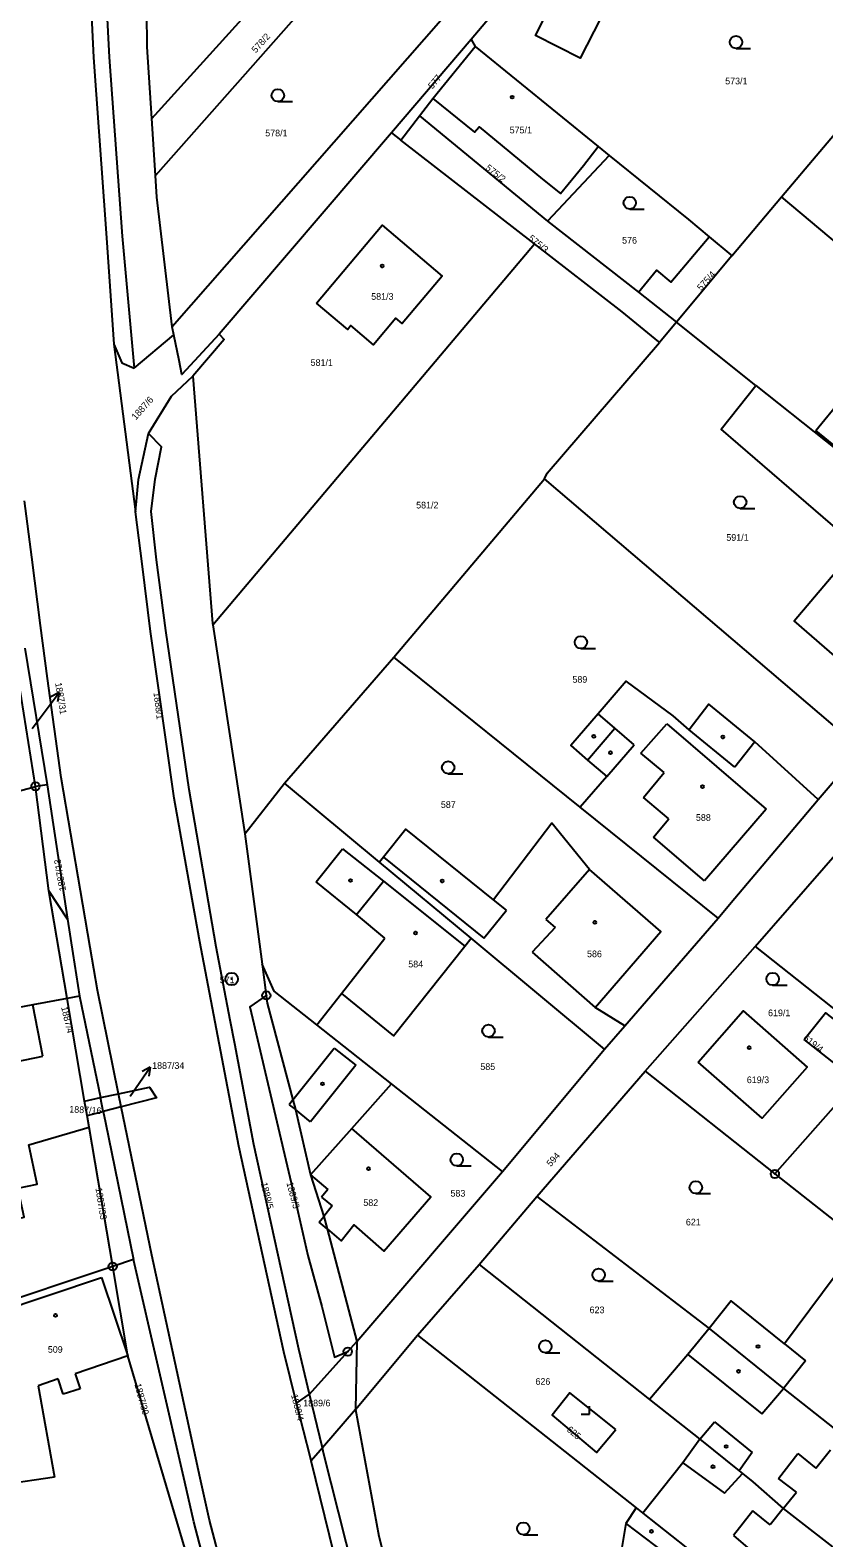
# Model space of a CAD drawing. Extents: x -587171 to -555306, y -1167727 to -1074732.
# Drawn here: x -561091.7 to -560995.9, y -1078068.2 to -1077886.5 of the extents above; entities that cross this region are included whole.
import ezdxf

# ---------------------------------------------------------------- set-up
doc = ezdxf.new("R2010")
doc.units = 0
for name, color, linetype in [('Hranice parcel', 7, 'Continuous'), ('Parcelní čísla', 7, 'Continuous'), ('Pop  PČ popisy', 7, 'Continuous'), ('Vnitřní kresba', 7, 'Continuous'), ('Značky bodu BP', 7, 'Continuous'), ('Značky budov', 7, 'Continuous'), ('Značky kultur', 7, 'Continuous')]:
    doc.layers.add(name, color=color, linetype=linetype)

msp = doc.modelspace()

# ---------------------------------------------------------------- linework, layer by layer
at = {"layer": 'Hranice parcel'}
for p, q in [((-561052.18, -1077876.5), (-561076.54, -1077904.04)), ((-561001.03, -1077906.61), (-560979.01, -1077880.52)), ((-561041.83, -1077885.03), (-561074.51, -1077922.26)), ((-561038.47, -1077887.64), (-561048.08, -1077898.88)), ((-561038.47, -1077887.64), (-561037.98, -1077888.46)), ((-561043.08, -1077894.73), (-561037.98, -1077888.46)), ((-561037.98, -1077888.46), (-561023.13, -1077900.55)), ((-561044.69, -1077896.83), (-561043.08, -1077894.73)), ((-561076.54, -1077904.04), (-561076.98, -1077897.15)), ((-561046.93, -1077899.77), (-561044.69, -1077896.83)), ((-561044.69, -1077896.83), (-561029.24, -1077909.55)), ((-561048.08, -1077898.88), (-561068.84, -1077923.15)), ((-561048.08, -1077898.88), (-561046.93, -1077899.77)), ((-561030.81, -1077912.27), (-561046.93, -1077899.77)), ((-561023.13, -1077900.55), (-561021.81, -1077901.62)), ((-561021.81, -1077901.62), (-561029.24, -1077909.55)), ((-561007.02, -1077913.69), (-561001.03, -1077906.61)), ((-560984.46, -1077920.52), (-561001.03, -1077906.61)), ((-561029.24, -1077909.55), (-561018.28, -1077918.07)), ((-561069.64, -1077958.17), (-561030.81, -1077912.27)), ((-561007.02, -1077913.69), (-561013.7, -1077921.7)), ((-561018.28, -1077918.07), (-561013.7, -1077921.7)), ((-561074.31, -1077923.24), (-561074.51, -1077922.26)), ((-561013.7, -1077921.7), (-561015.76, -1077924.17)), ((-561004.12, -1077929.33), (-561013.7, -1077921.7)), ((-561081.56, -1077924.36), (-561078.96, -1077944.55)), ((-561079.1, -1077927.23), (-561074.31, -1077923.24)), ((-561047.81, -1077962.07), (-561029.61, -1077940.57)), ((-560991.44, -1077973.16), (-561029.61, -1077940.57)), ((-561069.64, -1077958.17), (-561065.77, -1077983.36)), ((-561092.28, -1077961.01), (-561089.62, -1077977.48)), ((-561060.98, -1077977.27), (-561047.81, -1077962.07)), ((-561025.3, -1077980.17), (-561047.81, -1077962.07)), ((-561091.01, -1077977.66), (-561092.98, -1077965.31)), ((-561004.2, -1077996.95), (-560980.5, -1077969.74)), ((-560996.6, -1077979.25), (-560991.44, -1077973.16)), ((-561095.35, -1077978.85), (-561091.01, -1077977.66)), ((-561089.62, -1077977.48), (-561091.01, -1077977.66)), ((-561089.4, -1077990.23), (-561091.01, -1077977.66)), ((-561089.62, -1077977.48), (-561087.13, -1077993.66)), ((-561065.77, -1077983.36), (-561060.98, -1077977.27)), ((-561049.53, -1077986.79), (-561060.98, -1077977.27)), ((-561008.69, -1077993.53), (-561025.3, -1077980.17)), ((-561065.77, -1077983.36), (-561063.68, -1077999.09)), ((-561038.48, -1077995.97), (-561049.53, -1077986.79)), ((-561087.19, -1078003.22), (-561089.4, -1077990.23)), ((-561087.13, -1077993.66), (-561089.4, -1077990.23)), ((-561019.95, -1078006.54), (-561008.69, -1077993.53)), ((-561022.37, -1078009.35), (-561038.48, -1077995.97)), ((-561017.49, -1078012), (-561004.2, -1077996.95)), ((-561063.68, -1077999.09), (-561063.17, -1078002.86)), ((-561085.09, -1078015.6), (-561087.19, -1078003.22)), ((-561085.7, -1078002.94), (-561083.18, -1078015.18)), ((-561048.06, -1078013.52), (-561057.09, -1078006.39)), ((-561022.37, -1078009.35), (-561019.95, -1078006.54)), ((-561034.67, -1078024.09), (-561022.37, -1078009.35)), ((-561034.67, -1078024.09), (-561048.06, -1078013.52)), ((-561030.54, -1078027.08), (-561017.49, -1078012)), ((-561017.49, -1078012), (-561001.84, -1078024.37)), ((-561085.09, -1078015.6), (-561083.18, -1078015.18)), ((-561082.85, -1078016.84), (-561083.18, -1078015.18)), ((-561001.84, -1078024.37), (-560993.23, -1078014.63)), ((-561084.79, -1078017.33), (-561085.09, -1078015.6)), ((-561084.79, -1078017.33), (-561082.85, -1078016.84)), ((-561082.85, -1078016.84), (-561082.57, -1078018.16)), ((-561084.55, -1078018.75), (-561084.79, -1078017.33)), ((-561081.7, -1078035.53), (-561084.55, -1078018.75)), ((-561082.57, -1078018.16), (-561079.17, -1078034.69)), ((-561059.25, -1078045.49), (-561064.66, -1078020.81)), ((-561052.26, -1078044.56), (-561034.67, -1078024.09)), ((-561001.84, -1078024.37), (-560991.5, -1078032.54)), ((-561037.52, -1078035.3), (-561030.54, -1078027.08)), ((-561030.54, -1078027.08), (-561009.78, -1078042.99)), ((-561055.85, -1078031.01), (-561052.26, -1078044.56)), ((-561079.17, -1078034.69), (-561081.7, -1078035.53)), ((-561044.95, -1078043.79), (-561037.52, -1078035.3)), ((-561037.52, -1078035.3), (-561016.95, -1078051.57)), ((-561052.42, -1078052.76), (-561044.95, -1078043.79)), ((-561044.95, -1078043.79), (-561018.56, -1078064.64)), ((-561057.96, -1078050.91), (-561059.25, -1078045.49)), ((-561057.96, -1078050.91), (-561053.35, -1078045.78)), ((-561053.35, -1078045.78), (-561052.26, -1078044.56)), ((-561052.26, -1078044.56), (-561052.42, -1078052.76)), ((-561059.52, -1078052), (-561057.96, -1078050.91)), ((-561056.41, -1078057.37), (-561057.96, -1078050.91)), ((-561016.95, -1078051.57), (-561010.89, -1078056.36)), ((-561057.86, -1078058.61), (-561059.52, -1078052)), ((-561052.42, -1078052.76), (-561056.41, -1078057.37)), ((-561057.78, -1078058.97), (-561057.86, -1078058.61)), ((-561056.41, -1078057.37), (-561057.78, -1078058.97)), ((-561056.26, -1078058.01), (-561056.41, -1078057.37)), ((-561051.73, -1078083.29), (-561057.78, -1078058.97)), ((-561018.56, -1078064.64), (-561017.77, -1078065.26))]:
    msp.add_line(p, q, dxfattribs=at)
for points in [[(-561082.86, -1077794.3), (-561083.63, -1077819.25), (-561083.64, -1077849.26), (-561083.09, -1077871.28), (-561082.13, -1077889.75), (-561080.57, -1077911.33), (-561079.1, -1077927.23)], [(-561085.47, -1077819.26), (-561085.52, -1077849.15), (-561084.89, -1077871.39), (-561084.03, -1077889.81), (-561082.43, -1077911.55), (-561081.56, -1077924.36)], [(-561017.94, -1077863.52), (-561020.77, -1077866.7), (-561038.47, -1077887.64)], [(-561076.98, -1077897.15), (-561076.19, -1077896.27), (-561055.67, -1077873.63)], [(-561076.98, -1077897.15), (-561077.53, -1077888.51), (-561077.62, -1077880.12)], [(-561021.21, -1077881.85), (-561025.31, -1077889.9), (-561030.72, -1077887.15), (-561026.59, -1077879.07), (-561021.21, -1077881.85)], [(-561043.08, -1077894.73), (-561038.06, -1077898.82), (-561037.51, -1077898.15), (-561029.85, -1077904.45), (-561027.7, -1077906.2), (-561024.93, -1077902.81), (-561023.13, -1077900.55)], [(-561021.81, -1077901.62), (-561012.27, -1077909.35), (-561009.75, -1077911.42)], [(-561074.51, -1077922.26), (-561076.38, -1077906.62), (-561076.54, -1077904.04)], [(-561057.13, -1077919.4), (-561049.2, -1077910.03), (-561041.95, -1077916.15), (-561046.78, -1077921.86), (-561047.54, -1077921.24), (-561050.23, -1077924.42), (-561052.96, -1077922.12), (-561053.34, -1077922.59), (-561057.13, -1077919.4)], [(-561018.28, -1077918.07), (-561016.12, -1077915.44), (-561014.39, -1077916.89), (-561009.75, -1077911.42)], [(-561009.75, -1077911.42), (-561007.13, -1077913.59), (-561007.02, -1077913.69)], [(-561015.76, -1077924.17), (-561015.83, -1077924.08), (-561020.24, -1077920.46), (-561030.81, -1077912.27)], [(-561081.56, -1077924.36), (-561080.61, -1077926.59), (-561079.1, -1077927.23)], [(-561068.84, -1077923.15), (-561073.35, -1077928), (-561073.69, -1077926.32), (-561074.31, -1077923.24)], [(-561068.84, -1077923.15), (-561068.25, -1077923.78), (-561072.04, -1077928.22)], [(-561029.61, -1077940.57), (-561029.31, -1077939.9), (-561015.76, -1077924.17)], [(-561077.37, -1077935.13), (-561074.61, -1077930.64), (-561072.04, -1077928.22)], [(-561072.04, -1077928.22), (-561069.65, -1077958.03), (-561069.64, -1077958.17)], [(-560987.32, -1077968.28), (-560999.51, -1077957.72), (-560991.92, -1077948.75), (-561008.33, -1077934.6), (-561004.12, -1077929.33)], [(-561004.12, -1077929.33), (-560995.72, -1077936), (-560991.93, -1077939.08), (-560988.08, -1077942.22), (-560987.11, -1077942.82), (-560974.4, -1077953)], [(-560996.88, -1077934.75), (-560993.81, -1077931), (-560985.1, -1077938.11), (-560988.18, -1077941.87), (-560996.88, -1077934.75)], [(-561078.96, -1077944.55), (-561078.59, -1077940.66), (-561077.37, -1077935.13)], [(-561069.2, -1077997), (-561072.46, -1077978.04), (-561075.27, -1077958.88), (-561076.42, -1077950.34), (-561077.06, -1077944.53), (-561076.59, -1077940.62), (-561075.82, -1077936.75), (-561077.37, -1077935.13)], [(-561059.52, -1078052), (-561061.07, -1078045.8), (-561066.5, -1078021.01), (-561071.2, -1077996.41), (-561072.12, -1077991.25), (-561074.29, -1077979.09), (-561077.15, -1077959.01), (-561078.16, -1077950.83), (-561078.96, -1077944.55)], [(-560996.6, -1077979.25), (-561004.26, -1077972.27), (-561009.79, -1077967.76), (-561012.17, -1077970.83), (-561014.1, -1077969.17), (-561019.79, -1077964.97), (-561023.13, -1077968.9), (-561026.45, -1077972.73), (-561024.43, -1077974.48), (-561022.11, -1077976.48), (-561025.3, -1077980.17)], [(-561008.69, -1077993.53), (-561007.11, -1077991.66), (-560998.54, -1077981.54), (-560996.6, -1077979.25)], [(-561019.95, -1078006.54), (-561023.53, -1078004.3), (-561015.6, -1077995.14), (-561024.18, -1077987.69), (-561028.75, -1077982.09), (-561035.77, -1077991.32), (-561046.35, -1077982.8), (-561049.05, -1077986.19), (-561049.53, -1077986.79)], [(-561087.13, -1077993.66), (-561086.49, -1077997.81), (-561085.7, -1078002.94)], [(-561064.66, -1078020.81), (-561066.97, -1078008.68), (-561067.52, -1078005.82), (-561069.2, -1077997)], [(-561057.09, -1078006.39), (-561054.12, -1078002.63), (-561047.84, -1078007.72), (-561039.24, -1077996.92), (-561038.48, -1077995.97)], [(-561004.2, -1077996.95), (-560989.92, -1078008.3), (-560988.58, -1078009.37)], [(-561057.09, -1078006.39), (-561062.21, -1078002.36), (-561063.68, -1077999.09)], [(-561087.19, -1078003.22), (-561091.34, -1078004.01), (-561102.75, -1078006.17), (-561104.11, -1078008.44), (-561101.09, -1078021.08), (-561102.56, -1078021.43), (-561101.34, -1078026.53), (-561099.87, -1078026.18), (-561098.71, -1078031.02), (-561092.38, -1078029.6), (-561093.12, -1078026.09), (-561090.79, -1078025.6), (-561091.8, -1078020.88), (-561084.55, -1078018.75)], [(-561063.17, -1078002.86), (-561065.14, -1078004.23), (-561061.74, -1078018.76), (-561059.57, -1078028.01), (-561058.16, -1078034.2), (-561056.48, -1078040.37), (-561054.95, -1078046.47), (-561053.35, -1078045.78)], [(-561063.17, -1078002.86), (-561063.05, -1078003.77), (-561059.96, -1078015.45), (-561059.65, -1078016.62), (-561057.85, -1078024.48), (-561056.25, -1078029.49), (-561055.85, -1078031.01)], [(-561011.09, -1078010.9), (-561005.68, -1078004.73), (-560997.95, -1078011.5), (-561003.35, -1078017.66), (-561011.09, -1078010.9)], [(-560998.3, -1078008.18), (-560995.74, -1078004.97), (-560990.15, -1078009.35), (-560992.69, -1078012.59), (-560998.3, -1078008.18)], [(-561055.85, -1078031.01), (-561054.16, -1078032.45), (-561052.61, -1078030.52), (-561048.99, -1078033.69), (-561043.32, -1078027.14), (-561052.86, -1078018.9), (-561048.06, -1078013.52)], [(-561083.18, -1078015.18), (-561080.98, -1078014.71), (-561077.25, -1078013.9), (-561076.42, -1078015.22), (-561080.66, -1078016.29), (-561082.85, -1078016.84)], [(-560991.5, -1078032.54), (-561000.69, -1078044.87), (-561007.09, -1078039.66), (-561009.78, -1078042.99)], [(-561068.94, -1078077.68), (-561071.92, -1078066.3), (-561073.01, -1078061.54), (-561079.17, -1078034.69)], [(-561081.7, -1078035.53), (-561097.6, -1078040.85), (-561102.34, -1078042.43)], [(-561070.88, -1078078.07), (-561072.02, -1078072.73), (-561079.87, -1078046.29), (-561081.7, -1078035.53)], [(-561009.78, -1078042.99), (-561012.34, -1078046.14), (-561016.95, -1078051.57)], [(-561009.78, -1078042.99), (-561000.8, -1078050.22), (-560983.78, -1078063.65)], [(-561021.02, -1078055.19), (-561026.55, -1078050.75), (-561028.71, -1078053.47), (-561023.33, -1078057.95), (-561021.02, -1078055.19)], [(-561052.42, -1078052.76), (-561049.62, -1078068.03), (-561047.05, -1078077.92)], [(-561010.89, -1078056.36), (-561012.94, -1078059.21), (-561017.77, -1078065.26)], [(-561010.89, -1078056.36), (-561006.14, -1078060.15), (-561005.73, -1078060.47), (-561004.48, -1078061.5), (-561000.82, -1078064.69), (-560993.08, -1078070.74), (-560990.06, -1078073.1)], [(-561032.78, -1078117.8), (-561038.2, -1078116.25), (-561042.08, -1078112.32), (-561044.29, -1078104.96), (-561049.91, -1078083.09), (-561056.26, -1078058.01)], [(-561018.56, -1078064.64), (-561019.82, -1078066.52), (-561020.41, -1078070.11), (-561022.29, -1078072.09)], [(-561017.77, -1078065.26), (-561012.59, -1078069.36), (-560998.82, -1078080.16), (-560996.08, -1078082.31)]]:
    msp.add_lwpolyline(points, dxfattribs=at)
at = {"layer": 'Pop  PČ popisy'}
for p, q in [((-561089.96, -1077968.76), (-561088.15, -1077966.36)), ((-561088.15, -1077966.36), (-561089.16, -1077966.86)), ((-561088.15, -1077966.36), (-561088.36, -1077967.46)), ((-561091.43, -1077970.68), (-561089.96, -1077968.76)), ((-561078.88, -1078013.95), (-561077.16, -1078011.49)), ((-561077.16, -1078011.49), (-561078.14, -1078012.02)), ((-561077.16, -1078011.49), (-561077.32, -1078012.6)), ((-561079.6, -1078015), (-561078.88, -1078013.95))]:
    msp.add_line(p, q, dxfattribs=at)
at = {"layer": 'Vnitřní kresba'}
for p, q in [((-561091.45, -1077950.02), (-561092.32, -1077943.23)), ((-561090.39, -1077958.25), (-561091.45, -1077950.02)), ((-561089.57, -1077964.65), (-561090.39, -1077958.25)), ((-561087.92, -1077976.58), (-561089.57, -1077964.65)), ((-561021.12, -1077970.65), (-561023.13, -1077968.9)), ((-561024.43, -1077974.48), (-561021.12, -1077970.65)), ((-561018.8, -1077972.65), (-561021.12, -1077970.65)), ((-561017.99, -1077973.64), (-561014.85, -1077970.13)), ((-561014.85, -1077970.13), (-561002.89, -1077980.41)), ((-561006.66, -1077975.35), (-561012.17, -1077970.83)), ((-561022.11, -1077976.48), (-561018.8, -1077972.65)), ((-561004.26, -1077972.27), (-561006.66, -1077975.35)), ((-561015.2, -1077975.99), (-561017.99, -1077973.64)), ((-561017.69, -1077978.98), (-561015.2, -1077975.99)), ((-561014.64, -1077981.59), (-561017.69, -1077978.98)), ((-561002.89, -1077980.41), (-561010.32, -1077989.04)), ((-561016.49, -1077983.77), (-561014.64, -1077981.59)), ((-561010.32, -1077989.04), (-561016.49, -1077983.77)), ((-561057.14, -1077989.16), (-561053.97, -1077985.18)), ((-561053.97, -1077985.18), (-561049.04, -1077989.09)), ((-561049.05, -1077986.19), (-561036.95, -1077995.94)), ((-561024.18, -1077987.69), (-561029.45, -1077993.69)), ((-561052.28, -1077993.1), (-561057.14, -1077989.16)), ((-561052.28, -1077993.1), (-561049.04, -1077989.09)), ((-561049.04, -1077989.09), (-561039.24, -1077996.92)), ((-561034.22, -1077992.58), (-561035.77, -1077991.32)), ((-561048.86, -1077995.94), (-561052.28, -1077993.1)), ((-561036.95, -1077995.94), (-561034.22, -1077992.58)), ((-561028.35, -1077994.65), (-561031.09, -1077997.65)), ((-561029.45, -1077993.69), (-561028.35, -1077994.65)), ((-561054.12, -1078002.63), (-561048.86, -1077995.94)), ((-561031.09, -1077997.65), (-561023.53, -1078004.3)), ((-561083.54, -1078002.24), (-561083.98, -1077999.66)), ((-561080.98, -1078014.71), (-561083.54, -1078002.24)), ((-561090.12, -1078010.19), (-561091.34, -1078004.01)), ((-561085.7, -1078002.94), (-561087.19, -1078003.22)), ((-561059.96, -1078015.45), (-561054.97, -1078009.22)), ((-561054.97, -1078009.22), (-561052.39, -1078011.28)), ((-561096.56, -1078011.52), (-561090.12, -1078010.19)), ((-561052.39, -1078011.28), (-561057.86, -1078018.09)), ((-561080.66, -1078016.29), (-561080.98, -1078014.71)), ((-561076.99, -1078034.17), (-561080.66, -1078016.29)), ((-561059.96, -1078015.45), (-561060.43, -1078016.03)), ((-561060.43, -1078016.03), (-561059.65, -1078016.62)), ((-561057.86, -1078018.09), (-561059.65, -1078016.62)), ((-561052.86, -1078018.9), (-561057.85, -1078024.48)), ((-561057.85, -1078024.48), (-561055.77, -1078026.26)), ((-561055.77, -1078026.26), (-561056.53, -1078027.18)), ((-561056.53, -1078027.18), (-561055.22, -1078028.23)), ((-561056.81, -1078030.19), (-561056.25, -1078029.49)), ((-561055.22, -1078028.23), (-561056.25, -1078029.49)), ((-561055.85, -1078031.01), (-561056.81, -1078030.19)), ((-561071.14, -1078061.03), (-561076.99, -1078034.17)), ((-561097.35, -1078041.63), (-561083.05, -1078036.86)), ((-561083.05, -1078036.86), (-561079.87, -1078046.29)), ((-561012.34, -1078046.14), (-561003.4, -1078053.29)), ((-561000.69, -1078044.87), (-560998.16, -1078046.92)), ((-561079.87, -1078046.29), (-561086.22, -1078048.47)), ((-560998.16, -1078046.92), (-561000.8, -1078050.22)), ((-561088.26, -1078049.07), (-561090.7, -1078049.92)), ((-561087.66, -1078050.92), (-561088.26, -1078049.07)), ((-561086.22, -1078048.47), (-561085.64, -1078050.27)), ((-561090.7, -1078049.92), (-561088.7, -1078060.91)), ((-561085.64, -1078050.27), (-561087.66, -1078050.92)), ((-561003.4, -1078053.29), (-561000.8, -1078050.22)), ((-561010.89, -1078056.36), (-561009.12, -1078054.25)), ((-561009.12, -1078054.25), (-561004.58, -1078057.97)), ((-561004.58, -1078057.97), (-561006.14, -1078060.15)), ((-561001.38, -1078061.08), (-560999.05, -1078058.09)), ((-560999.05, -1078058.09), (-560996.88, -1078059.83)), ((-560996.88, -1078059.83), (-560995.11, -1078057.64)), ((-561012.94, -1078059.21), (-561007.92, -1078062.87)), ((-561007.92, -1078062.87), (-561005.73, -1078060.47)), ((-561088.7, -1078060.91), (-561094.7, -1078061.79)), ((-561070.04, -1078066.09), (-561071.14, -1078061.03)), ((-560999.24, -1078062.75), (-561001.38, -1078061.08)), ((-561000.82, -1078064.69), (-560999.24, -1078062.75)), ((-561067.09, -1078077.12), (-561070.04, -1078066.09)), ((-561004.49, -1078064.99), (-561006.83, -1078067.94)), ((-561002.4, -1078066.67), (-561004.49, -1078064.99)), ((-561000.82, -1078064.69), (-561002.4, -1078066.67)), ((-561019.82, -1078066.52), (-561015.15, -1078070.06)), ((-561006.83, -1078067.94), (-561004.83, -1078069.7))]:
    msp.add_line(p, q, dxfattribs=at)
msp.add_lwpolyline([(-561083.98, -1077999.66), (-561084.42, -1077997.08), (-561087.92, -1077976.58)], dxfattribs=at)
at = {"layer": 'Značky bodu BP'}
for centre, radius in [((-561091.01, -1077977.66), 0.5), ((-561091.01, -1077977.66), 0.0303), ((-561067.35, -1078000.88), 0.75), ((-561067.35, -1078000.88), 0.03), ((-561063.17, -1078002.86), 0.5), ((-561063.17, -1078002.86), 0.0303), ((-561001.84, -1078024.37), 0.5), ((-561001.84, -1078024.37), 0.0303), ((-561081.7, -1078035.53), 0.5), ((-561081.7, -1078035.53), 0.0303), ((-561053.35, -1078045.78), 0.5), ((-561053.35, -1078045.78), 0.0303)]:
    msp.add_circle(centre, radius, dxfattribs=at)
at = {"layer": 'Značky budov'}
for centre in [(-561033.52, -1077894.58), (-561049.21, -1077914.93), (-561023.68, -1077971.63), (-561008.13, -1077971.7), (-561021.65, -1077973.61), (-561010.56, -1077977.69), (-561053.03, -1077989), (-561041.97, -1077989.06), (-561045.19, -1077995.34), (-561023.56, -1077994.06), (-561004.95, -1078009.16), (-561056.39, -1078013.51), (-561050.86, -1078023.75), (-561088.6, -1078041.42), (-561003.87, -1078045.17), (-561006.23, -1078048.16), (-561007.71, -1078057.23), (-561009.3, -1078059.67), (-561016.71, -1078067.46)]:
    msp.add_circle(centre, 0.175, dxfattribs=at)
at = {"layer": 'Značky kultur'}
for p, q in [((-561006.52, -1077888.71), (-561004.77, -1077888.71)), ((-561061.78, -1077895.12), (-561060.03, -1077895.12)), ((-561019.34, -1077908.08), (-561017.59, -1077908.08)), ((-561006.02, -1077944.16), (-561004.27, -1077944.16)), ((-561025.23, -1077961.04), (-561023.48, -1077961.04)), ((-561041.24, -1077976.14), (-561039.49, -1077976.14)), ((-561002.11, -1078001.62), (-561000.36, -1078001.62)), ((-561036.37, -1078007.87), (-561034.62, -1078007.87)), ((-561040.2, -1078023.41), (-561038.45, -1078023.41)), ((-561011.37, -1078026.74), (-561009.62, -1078026.74)), ((-561023.09, -1078037.29), (-561021.34, -1078037.29)), ((-561029.52, -1078045.92), (-561027.77, -1078045.92)), ((-561025.18, -1078053.35), (-561024.18, -1078053.35)), ((-561024.18, -1078053.35), (-561024.18, -1078052.35)), ((-561032.17, -1078067.87), (-561030.42, -1078067.87))]:
    msp.add_line(p, q, dxfattribs=at)
for centre in [(-561006.52, -1077887.96), (-561061.78, -1077894.37), (-561019.34, -1077907.33), (-561006.02, -1077943.41), (-561025.23, -1077960.29), (-561041.24, -1077975.39), (-561002.11, -1078000.87), (-561036.37, -1078007.12), (-561040.2, -1078022.66), (-561011.37, -1078025.99), (-561023.09, -1078036.54), (-561029.52, -1078045.17), (-561032.17, -1078067.12)]:
    msp.add_circle(centre, 0.75, dxfattribs=at)

# ---------------------------------------------------------------- texts
at = {"layer": 'Parcelní čísla'}
for s, rotation, p in [('578/2', 48, (-561064.44, -1077889.32)), ('577', 50, (-561043.14, -1077893.67)), ('575/2', 322, (-561036.81, -1077903.25)), ('575/3', 321, (-561031.65, -1077911.72)), ('575/4', 48, (-561010.72, -1077917.99)), ('1887/6', 48, (-561078.91, -1077933.55)), ('1887/31', 279, (-561088.64, -1077965.2)), ('1888/1', 277, (-561076.78, -1077966.36)), ('1887/13', 100, (-561087.32, -1077990.21)), ('1887/4', 283, (-561087.92, -1078004.28)), ('619/4', 322, (-560998.51, -1078008.14)), ('1887/16', 357, (-561086.95, -1078016.96)), ('594', 48, (-561028.87, -1078023.56)), ('1887/33', 279, (-561083.78, -1078026.1)), ('1889/5', 284, (-561063.85, -1078025.49)), ('1889/3', 285, (-561060.75, -1078025.46)), ('1887/30', 285, (-561079.08, -1078049.74)), ('1888/4', 284, (-561060.19, -1078051.02)), ('625', 320, (-561027.01, -1078055.31))]:
    msp.add_text(s, height=0.803, rotation=rotation, dxfattribs=at).set_placement(p)
for s, p in [('573/1', (-561007.83, -1077893.04)), ('578/1', (-561063.3, -1077899.31)), ('575/1', (-561033.82, -1077898.95)), ('576', (-561020.26, -1077912.24)), ('581/3', (-561050.52, -1077919.01)), ('581/1', (-561057.83, -1077926.98)), ('581/2', (-561045.1, -1077944.16)), ('591/1', (-561007.69, -1077948.06)), ('589', (-561026.25, -1077965.17)), ('587', (-561042.12, -1077980.25)), ('588', (-561011.36, -1077981.81)), ('584', (-561046.05, -1077999.48)), ('586', (-561024.49, -1077998.25)), ('619/1', (-561002.66, -1078005.36)), ('1887/34', (-561076.94, -1078011.71)), ('585', (-561037.36, -1078011.84)), ('619/3', (-561005.22, -1078013.43)), ('582', (-561051.47, -1078028.23)), ('583', (-561040.96, -1078027.11)), ('621', (-561012.57, -1078030.58)), ('623', (-561024.18, -1078041.16)), ('509', (-561089.52, -1078045.93)), ('626', (-561030.71, -1078049.79)), ('1889/6', (-561058.72, -1078052.39))]:
    msp.add_text(s, height=0.803, dxfattribs=at).set_placement(p)
at = {"layer": 'Značky bodu BP'}
msp.add_text('571', height=0.803, dxfattribs=at).set_placement((-561068.79, -1078001.38))

doc.saveas('drawing.dxf')
